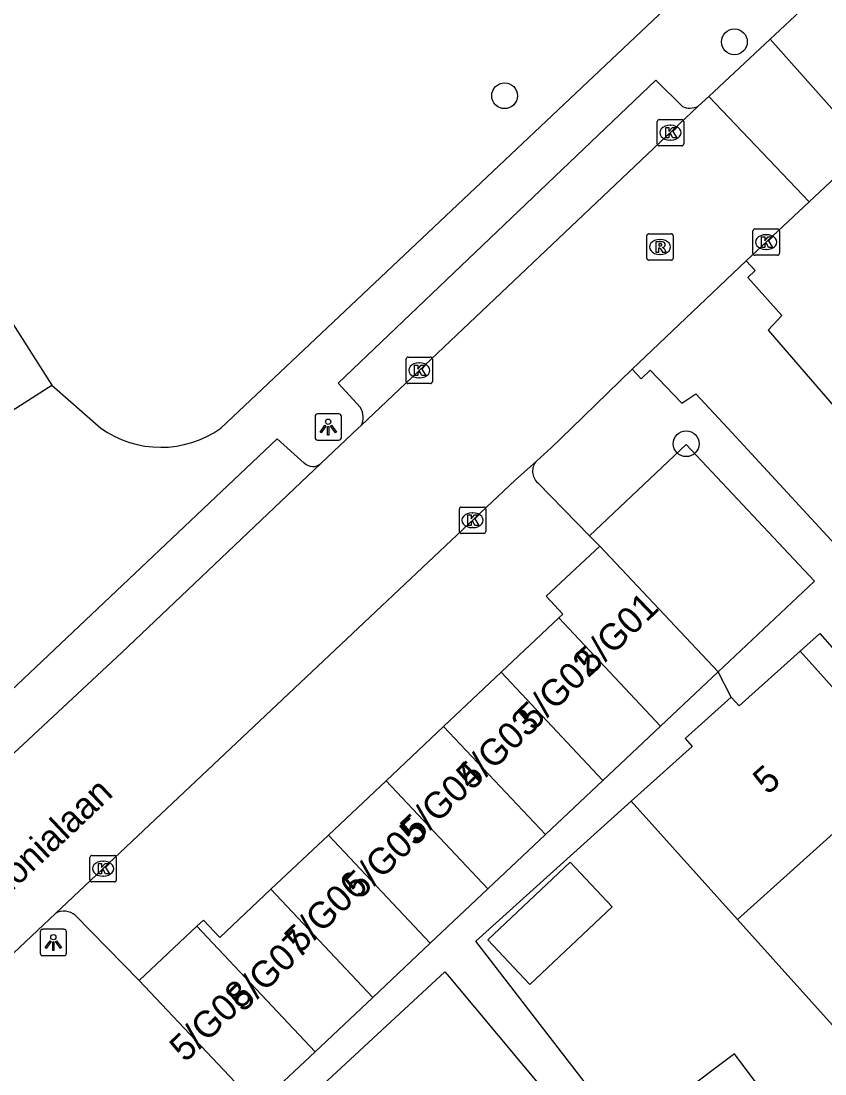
# Model space of a CAD drawing. Extents: x 162347 to 162868, y 381221 to 381813.
# Drawn here: x 162597.89 to 162628.37, y 381475.54 to 381515.43 of the extents above; entities that cross this region are included whole.
import ezdxf

# ---------------------------------------------------------------- set-up
doc = ezdxf.new("R2010")
doc.units = 0
for name, color, linetype in [('IMGEO_Boom', 7, 'Continuous'), ('IMGEO_Hek', 7, 'Continuous'), ('IMGEO_Kolk', 7, 'Continuous'), ('IMGEO_Lichtpunt', 7, 'Continuous'), ('IMGEO_Openbare_ruimte_label', 7, 'Continuous'), ('IMGEO_Pand', 7, 'Continuous'), ('IMGEO_Pand_nummerreeks', 7, 'Continuous'), ('IMGEO_Rijbaan_lokaal_gesloten', 7, 'Continuous'), ('IMGEO_Rijbaan_lokaal_open', 7, 'Continuous'), ('IMGEO_Rioolput', 7, 'Continuous'), ('IMGEO_Voetpad_open', 7, 'Continuous')]:
    doc.layers.add(name, color=color, linetype=linetype)

msp = doc.modelspace()

# ---------------------------------------------------------------- linework, layer by layer
at = {"layer": 'IMGEO_Boom'}
for centre in [(162624.937, 381514.64), (162616.225, 381512.599), (162623.108, 381499.413)]:
    msp.add_circle(centre, 0.489, dxfattribs=at)
at = {"layer": 'IMGEO_Hek'}
msp.add_lwpolyline([(162599.059, 381501.63), (162600.915, 381500.002)], dxfattribs=at)
at = {"layer": 'IMGEO_Kolk'}
for p, q in [((162622.012, 381510.771), (162622.012, 381511.623)), ((162622.087, 381511.697), (162622.939, 381511.697)), ((162622.5, 381511.477), (162622.525, 381511.477)), ((162623.013, 381511.623), (162623.013, 381510.771)), ((162622.523, 381510.917), (162622.498, 381510.917)), ((162622.939, 381510.697), (162622.087, 381510.697)), ((162625.64, 381506.627), (162625.64, 381507.479)), ((162625.715, 381507.553), (162626.567, 381507.553)), ((162626.128, 381507.333), (162626.153, 381507.333)), ((162626.641, 381507.479), (162626.641, 381506.627)), ((162626.567, 381506.553), (162625.715, 381506.553)), ((162626.151, 381506.773), (162626.126, 381506.773)), ((162612.49, 381501.767), (162612.49, 381502.619)), ((162612.565, 381502.693), (162613.417, 381502.693)), ((162613.491, 381502.619), (162613.491, 381501.767)), ((162612.978, 381502.473), (162613.003, 381502.473)), ((162613.001, 381501.913), (162612.976, 381501.913)), ((162613.417, 381501.693), (162612.565, 381501.693)), ((162614.509, 381496.088), (162614.509, 381496.94)), ((162614.584, 381497.014), (162615.436, 381497.014)), ((162615.51, 381496.94), (162615.51, 381496.088)), ((162614.997, 381496.794), (162615.022, 381496.794)), ((162615.02, 381496.234), (162614.995, 381496.234)), ((162615.436, 381496.014), (162614.584, 381496.014)), ((162600.58, 381483.813), (162601.432, 381483.813)), ((162600.505, 381482.887), (162600.505, 381483.739)), ((162600.993, 381483.593), (162601.018, 381483.593)), ((162601.506, 381483.739), (162601.506, 381482.887)), ((162601.016, 381483.033), (162600.991, 381483.033)), ((162601.432, 381482.813), (162600.58, 381482.813))]:
    msp.add_line(p, q, dxfattribs=at)
for points in [[(162622.012, 381510.771), (162622.012, 381511.623)], [(162622.087, 381511.697), (162622.939, 381511.697)], [(162622.333, 381511.397), (162622.456, 381511.397), (162622.456, 381511.246), (162622.586, 381511.397), (162622.75, 381511.397), (162622.604, 381511.246), (162622.757, 381510.997), (162622.605, 381510.997), (162622.52, 381511.161), (162622.456, 381511.094), (162622.456, 381510.997), (162622.333, 381510.997), (162622.333, 381511.397)], [(162623.013, 381511.623), (162623.013, 381510.771)], [(162622.939, 381510.697), (162622.087, 381510.697)], [(162625.64, 381506.627), (162625.64, 381507.479)], [(162625.715, 381507.553), (162626.567, 381507.553)], [(162626.641, 381507.479), (162626.641, 381506.627)], [(162625.961, 381507.253), (162626.084, 381507.253), (162626.084, 381507.102), (162626.214, 381507.253), (162626.378, 381507.253), (162626.232, 381507.102), (162626.385, 381506.853), (162626.233, 381506.853), (162626.148, 381507.017), (162626.084, 381506.95), (162626.084, 381506.853), (162625.961, 381506.853), (162625.961, 381507.253)], [(162626.567, 381506.553), (162625.715, 381506.553)], [(162612.49, 381501.767), (162612.49, 381502.619)], [(162612.565, 381502.693), (162613.417, 381502.693)], [(162613.491, 381502.619), (162613.491, 381501.767)], [(162612.811, 381502.393), (162612.934, 381502.393), (162612.934, 381502.242), (162613.064, 381502.393), (162613.228, 381502.393), (162613.082, 381502.242), (162613.235, 381501.993), (162613.083, 381501.993), (162612.998, 381502.157), (162612.934, 381502.09), (162612.934, 381501.993), (162612.811, 381501.993), (162612.811, 381502.393)], [(162613.417, 381501.693), (162612.565, 381501.693)], [(162614.509, 381496.088), (162614.509, 381496.94)], [(162614.584, 381497.014), (162615.436, 381497.014)], [(162615.51, 381496.94), (162615.51, 381496.088)], [(162614.83, 381496.714), (162614.953, 381496.714), (162614.953, 381496.563), (162615.083, 381496.714), (162615.247, 381496.714), (162615.101, 381496.563), (162615.254, 381496.314), (162615.102, 381496.314), (162615.017, 381496.478), (162614.953, 381496.411), (162614.953, 381496.314), (162614.83, 381496.314), (162614.83, 381496.714)], [(162615.436, 381496.014), (162614.584, 381496.014)], [(162600.58, 381483.813), (162601.432, 381483.813)], [(162600.505, 381482.887), (162600.505, 381483.739)], [(162600.826, 381483.513), (162600.949, 381483.513), (162600.949, 381483.362), (162601.079, 381483.513), (162601.243, 381483.513), (162601.097, 381483.362), (162601.25, 381483.113), (162601.098, 381483.113), (162601.013, 381483.277), (162600.949, 381483.21), (162600.949, 381483.113), (162600.826, 381483.113), (162600.826, 381483.513)], [(162601.506, 381483.739), (162601.506, 381482.887)], [(162601.432, 381482.813), (162600.58, 381482.813)]]:
    msp.add_lwpolyline(points, dxfattribs=at)
for centre, start, end in [((162622.089, 381511.621), 91.552, 178.448), ((162622.089, 381511.621), 91.552, 178.448), ((162622.937, 381511.621), 1.552, 88.448), ((162622.937, 381511.621), 1.552, 88.448), ((162622.089, 381510.773), 181.552, 268.448), ((162622.089, 381510.773), 181.552, 268.448), ((162622.937, 381510.773), 271.552, 358.448), ((162622.937, 381510.773), 271.552, 358.448), ((162625.717, 381507.477), 91.552, 178.448), ((162625.717, 381507.477), 91.552, 178.448), ((162626.565, 381507.477), 1.552, 88.448), ((162626.565, 381507.477), 1.552, 88.448), ((162625.717, 381506.629), 181.552, 268.448), ((162625.717, 381506.629), 181.552, 268.448), ((162626.565, 381506.629), 271.552, 358.448), ((162626.565, 381506.629), 271.552, 358.448), ((162612.567, 381502.617), 91.552, 178.448), ((162612.567, 381502.617), 91.552, 178.448), ((162613.415, 381502.617), 1.552, 88.448), ((162613.415, 381502.617), 1.552, 88.448), ((162612.567, 381501.769), 181.552, 268.448), ((162612.567, 381501.769), 181.552, 268.448), ((162613.415, 381501.769), 271.552, 358.448), ((162613.415, 381501.769), 271.552, 358.448), ((162614.586, 381496.938), 91.552, 178.448), ((162614.586, 381496.938), 91.552, 178.448), ((162615.434, 381496.938), 1.552, 88.448), ((162615.434, 381496.938), 1.552, 88.448), ((162614.586, 381496.09), 181.552, 268.448), ((162614.586, 381496.09), 181.552, 268.448), ((162615.434, 381496.09), 271.552, 358.448), ((162615.434, 381496.09), 271.552, 358.448), ((162600.582, 381483.737), 91.552, 178.448), ((162600.582, 381483.737), 91.552, 178.448), ((162601.43, 381483.737), 1.552, 88.448), ((162601.43, 381483.737), 1.552, 88.448), ((162600.582, 381482.889), 181.552, 268.448), ((162600.582, 381482.889), 181.552, 268.448), ((162601.43, 381482.889), 271.552, 358.448), ((162601.43, 381482.889), 271.552, 358.448)]:
    msp.add_arc(centre, 0.0765, start, end, dxfattribs=at)
for centre, major_axis, ratio, start_param, end_param in [((162622.499, 381511.197), (-0.387, 0.002), 0.722429, 4.712389, 7.853982), ((162622.524, 381511.197), (-0.39, 0.002), 0.717154, 1.570796, 4.712389), ((162626.127, 381507.053), (-0.387, 0.002), 0.722429, 4.712389, 7.853982), ((162626.152, 381507.053), (-0.39, 0.002), 0.717154, 1.570796, 4.712389), ((162612.977, 381502.193), (-0.387, 0.002), 0.722429, 4.712389, 7.853982), ((162613.002, 381502.193), (-0.39, 0.002), 0.717154, 1.570796, 4.712389), ((162614.996, 381496.514), (-0.387, 0.002), 0.722429, 4.712389, 7.853982), ((162615.021, 381496.514), (-0.39, 0.002), 0.717154, 1.570796, 4.712389), ((162600.992, 381483.313), (-0.387, 0.002), 0.722429, 4.712389, 7.853982), ((162601.017, 381483.313), (-0.39, 0.002), 0.717154, 1.570796, 4.712389)]:
    msp.add_ellipse(centre, major_axis=major_axis, ratio=ratio, start_param=start_param, end_param=end_param, dxfattribs=at)
at = {"layer": 'IMGEO_Lichtpunt'}
for p, q in [((162609.942, 381500.544), (162609.134, 381500.544)), ((162609.942, 381500.544), (162609.134, 381500.544)), ((162609.04, 381500.449), (162609.04, 381499.642)), ((162609.04, 381500.449), (162609.04, 381499.642)), ((162610.036, 381499.642), (162610.036, 381500.449)), ((162610.036, 381499.642), (162610.036, 381500.449)), ((162609.134, 381499.548), (162609.942, 381499.548)), ((162609.134, 381499.548), (162609.942, 381499.548)), ((162599.522, 381481.015), (162598.714, 381481.015)), ((162599.522, 381481.015), (162598.714, 381481.015)), ((162598.62, 381480.92), (162598.62, 381480.113)), ((162598.62, 381480.92), (162598.62, 381480.113)), ((162599.616, 381480.113), (162599.616, 381480.92)), ((162599.616, 381480.113), (162599.616, 381480.92)), ((162598.714, 381480.019), (162599.522, 381480.019)), ((162598.714, 381480.019), (162599.522, 381480.019))]:
    msp.add_line(p, q, dxfattribs=at)
for points in [[(162609.414, 381500.113), (162609.453, 381500.085), (162609.265, 381499.823), (162609.227, 381499.85), (162609.414, 381500.113)], [(162609.516, 381500.065), (162609.563, 381500.065), (162609.563, 381499.743), (162609.516, 381499.743), (162609.516, 381500.065)], [(162609.626, 381500.085), (162609.664, 381500.112), (162609.851, 381499.85), (162609.812, 381499.822), (162609.626, 381500.085)], [(162598.994, 381480.584), (162599.033, 381480.556), (162598.845, 381480.294), (162598.807, 381480.321), (162598.994, 381480.584)], [(162599.206, 381480.556), (162599.244, 381480.583), (162599.431, 381480.321), (162599.392, 381480.293), (162599.206, 381480.556)], [(162599.096, 381480.536), (162599.143, 381480.536), (162599.143, 381480.214), (162599.096, 381480.214), (162599.096, 381480.536)]]:
    msp.add_lwpolyline(points, dxfattribs=at)
for centre in [(162609.539, 381500.247), (162599.119, 381480.718)]:
    msp.add_circle(centre, 0.0994, dxfattribs=at)
for centre, start, end in [((162609.134, 381500.449), 90, 180), ((162609.134, 381500.449), 90, 180), ((162609.942, 381500.449), 0, 90), ((162609.942, 381500.449), 0, 90), ((162609.134, 381499.642), 180, 270), ((162609.134, 381499.642), 180, 270), ((162609.942, 381499.642), 270, 0), ((162609.942, 381499.642), 270, 360), ((162598.714, 381480.92), 90, 180), ((162598.714, 381480.92), 90, 180), ((162599.522, 381480.92), 0, 90), ((162599.522, 381480.92), 0, 90), ((162598.714, 381480.113), 180, 270), ((162598.714, 381480.113), 180, 270), ((162599.522, 381480.113), 270, 0), ((162599.522, 381480.113), 270, 360)]:
    msp.add_arc(centre, 0.0946, start, end, dxfattribs=at)
at = {"layer": 'IMGEO_Pand'}
for points in [[(162589.643, 381516.415), (162599.059, 381501.63)], [(162590.956, 381496.468), (162596.5, 381500), (162599.059, 381501.63)], [(162619.829, 381495.538), (162617.804, 381493.632), (162618.437, 381492.96), (162618.279, 381492.811)], [(162624.32, 381490.769), (162619.829, 381495.538)], [(162618.279, 381492.811), (162616.096, 381490.755)], [(162622.137, 381488.713), (162618.279, 381492.811)], [(162627.423, 381491.558), (162625.117, 381489.484), (162624.818, 381489.816)], [(162631.421, 381487.111), (162627.423, 381491.558)], [(162616.096, 381490.755), (162613.913, 381488.699)], [(162616.096, 381490.755), (162619.954, 381486.658)], [(162624.32, 381490.769), (162622.137, 381488.713)], [(162624.818, 381489.816), (162623.071, 381488.245), (162623.339, 381487.948), (162621.027, 381485.869)], [(162613.913, 381488.699), (162611.73, 381486.644)], [(162617.772, 381484.602), (162613.913, 381488.699)], [(162619.954, 381486.658), (162622.137, 381488.713)], [(162625.059, 381481.385), (162631.421, 381487.111)], [(162611.73, 381486.644), (162609.548, 381484.588)], [(162611.73, 381486.644), (162615.589, 381482.546)], [(162617.772, 381484.602), (162619.954, 381486.658)], [(162621.027, 381485.869), (162625.059, 381481.385)], [(162609.548, 381484.588), (162607.365, 381482.532)], [(162613.406, 381480.491), (162609.548, 381484.588)], [(162615.589, 381482.546), (162617.772, 381484.602)], [(162617.184, 381478.926), (162615.585, 381480.622), (162618.707, 381483.565), (162620.307, 381481.869), (162617.184, 381478.926)], [(162607.365, 381482.532), (162605.427, 381480.707), (162604.805, 381481.367), (162604.561, 381481.137)], [(162611.224, 381478.435), (162607.365, 381482.532)], [(162615.589, 381482.546), (162613.406, 381480.491)], [(162628.767, 381477.262), (162625.059, 381481.385)], [(162602.378, 381479.081), (162604.561, 381481.137)], [(162604.561, 381481.137), (162609.041, 381476.38)], [(162611.224, 381478.435), (162613.406, 381480.491)], [(162602.378, 381479.081), (162606.858, 381474.324)], [(162609.041, 381476.38), (162611.224, 381478.435)], [(162609.041, 381476.38), (162606.858, 381474.324)], [(162626.184, 381474.649), (162624.944, 381476.3), (162620.826, 381473.208)]]:
    msp.add_lwpolyline(points, dxfattribs=at)
at = {"layer": 'IMGEO_Rijbaan_lokaal_gesloten'}
for points in [[(162626.296, 381514.744), (162630.602, 381518.772), (162630.767, 381518.982)], [(162623.562, 381512.202), (162623.969, 381512.568)], [(162610.782, 381500.101), (162623.562, 381512.202)], [(162627.765, 381508.572), (162625.383, 381506.346)], [(162621.057, 381502.239), (162625.383, 381506.346)], [(162617.432, 381498.758), (162617.995, 381499.26), (162618.756, 381500), (162621.057, 381502.239)], [(162609.259, 381498.658), (162610.676, 381500), (162610.782, 381500.101)], [(162597.236, 381487.337), (162601.705, 381491.492), (162609.259, 381498.658)], [(162617.432, 381498.758), (162616.622, 381498.036), (162602.541, 381484.756), (162599.198, 381481.618)], [(162596.295, 381478.884), (162596.456, 381479.044), (162599.198, 381481.618)]]:
    msp.add_lwpolyline(points, dxfattribs=at)
at = {"layer": 'IMGEO_Rijbaan_lokaal_open'}
for points in [[(162623.969, 381512.568), (162626.296, 381514.744)], [(162629.957, 381510.619), (162626.296, 381514.744)], [(162627.765, 381508.572), (162623.969, 381512.568)], [(162629.957, 381510.619), (162627.765, 381508.572)], [(162625.383, 381506.346), (162625.724, 381505.981), (162625.443, 381505.714), (162626.74, 381504.271), (162626.215, 381503.718), (162629.428, 381500), (162632.112, 381496.894)], [(162621.057, 381502.239), (162621.398, 381501.874), (162621.74, 381502.2), (162622.948, 381500.954), (162623.472, 381501.309), (162624.682, 381500), (162629.654, 381494.622)]]:
    msp.add_lwpolyline(points, dxfattribs=at)
at = {"layer": 'IMGEO_Rioolput'}
for p, q in [((162621.69, 381507.368), (162622.542, 381507.368)), ((162621.615, 381506.442), (162621.615, 381507.294)), ((162622.103, 381507.148), (162622.128, 381507.148)), ((162622.616, 381507.294), (162622.616, 381506.442)), ((162622.126, 381506.588), (162622.101, 381506.588)), ((162622.542, 381506.368), (162621.69, 381506.368))]:
    msp.add_line(p, q, dxfattribs=at)
for points in [[(162621.69, 381507.368), (162622.542, 381507.368)], [(162621.615, 381506.442), (162621.615, 381507.294)], [(162622.204, 381507.066), (162621.952, 381507.068), (162621.952, 381506.668)], [(162622.13, 381506.987), (162622.076, 381506.987), (162622.076, 381506.906)], [(162622.616, 381507.294), (162622.616, 381506.442)], [(162621.952, 381506.668), (162622.076, 381506.668), (162622.076, 381506.83), (162622.087, 381506.83)], [(162622.076, 381506.906), (162622.128, 381506.906)], [(162622.134, 381506.801), (162622.205, 381506.668), (162622.345, 381506.668), (162622.28, 381506.794)], [(162622.542, 381506.368), (162621.69, 381506.368)]]:
    msp.add_lwpolyline(points, dxfattribs=at)
for centre, radius, start, end in [((162621.692, 381507.292), 0.0765, 91.552, 178.448), ((162621.692, 381507.292), 0.0765, 91.552, 178.448), ((162622.54, 381507.292), 0.0765, 1.552, 88.448), ((162622.54, 381507.292), 0.0765, 1.552, 88.448), ((162622.136, 381506.891), 0.0964, 77.0061, 93.1865), ((162622.15, 381506.948), 0.0378, 276.6634, 79.6772), ((162622.203, 381506.956), 0.109, 350.3612, 89.416), ((162622.201, 381506.956), 0.112, 277.5842, 350.9817), ((162622.086, 381506.777), 0.0533, 26.0293, 88.6989), ((162622.112, 381507.095), 0.19, 274.7715, 282.9687), ((162622.185, 381506.741), 0.108, 29.5134, 73.7905), ((162621.692, 381506.444), 0.0765, 181.552, 268.448), ((162621.692, 381506.444), 0.0765, 181.552, 268.448), ((162622.54, 381506.444), 0.0765, 271.552, 358.448), ((162622.54, 381506.444), 0.0765, 271.552, 358.448)]:
    msp.add_arc(centre, radius, start, end, dxfattribs=at)
for centre, major_axis, ratio, start_param, end_param in [((162622.102, 381506.868), (-0.387, 0.002), 0.722429, 4.712389, 7.853982), ((162622.127, 381506.868), (-0.39, 0.002), 0.717154, 1.570796, 4.712389)]:
    msp.add_ellipse(centre, major_axis=major_axis, ratio=ratio, start_param=start_param, end_param=end_param, dxfattribs=at)
at = {"layer": 'IMGEO_Voetpad_open'}
for points in [[(162605.462, 381500), (162622.742, 381516.31)], [(162622.964, 381512.195), (162621.954, 381513.191), (162609.913, 381501.714), (162610.757, 381500.78)], [(162599.059, 381501.63), (162600.915, 381500.002)], [(162608.627, 381498.683), (162607.605, 381499.602), (162596.332, 381488.956)], [(162624.32, 381490.769), (162627.975, 381494.211), (162623.107, 381499.381), (162619.438, 381495.925)], [(162619.438, 381495.925), (162617.48, 381497.935)], [(162619.829, 381495.538), (162619.438, 381495.925)], [(162627.423, 381491.558), (162628.17, 381492.223), (162634.659, 381484.876)], [(162624.818, 381489.816), (162624.32, 381490.769)], [(162620.826, 381473.208), (162615.133, 381480.569), (162621.027, 381485.869)], [(162599.95, 381481.55), (162602.378, 381479.081)], [(162607.642, 381473.555), (162613.96, 381479.407), (162614.124, 381479.21), (162618.804, 381473.616)]]:
    msp.add_lwpolyline(points, dxfattribs=at)
for centre, radius, start, end in [((162623.256, 381512.797), 0.669, 244.1355, 297.2058), ((162610.193, 381500.419), 0.67, 331.6258, 32.5914), ((162603.19, 381503.214), 3.936, 234.6922, 305.2574), ((162608.957, 381499.025), 0.475, 225.9852, 309.4843), ((162617.866, 381498.37), 0.582, 138.2134, 228.4623), ((162599.523, 381481.015), 0.685, 51.3841, 118.282)]:
    msp.add_arc(centre, radius, start, end, dxfattribs=at)

# ---------------------------------------------------------------- texts
at = {"layer": 'IMGEO_Openbare_ruimte_label'}
msp.add_text('Cydonialaan', height=1, rotation=43.2986, dxfattribs=at).set_placement((162596.025, 381481.006))
at = {"layer": 'IMGEO_Pand_nummerreeks'}
for s, rotation, p in [('5/G01', 43.8485, (162619.502, 381490.617)), ('5/G02', 43.8485, (162617.303, 381488.505)), ('5/G03', 43.8485, (162614.983, 381486.251)), ('5/G04', 43.8485, (162612.862, 381484.241)), ('5', 41.6519, (162626.199, 381486.08)), ('5/G05', 43.8485, (162610.74, 381482.12)), ('5/G06', 43.8485, (162608.47, 381480.073)), ('5/G07', 43.8485, (162606.311, 381477.84)), ('5/G08', 43.8485, (162604.118, 381475.944))]:
    msp.add_text(s, height=1, rotation=rotation, dxfattribs=at).set_placement(p)

doc.saveas('drawing.dxf')
